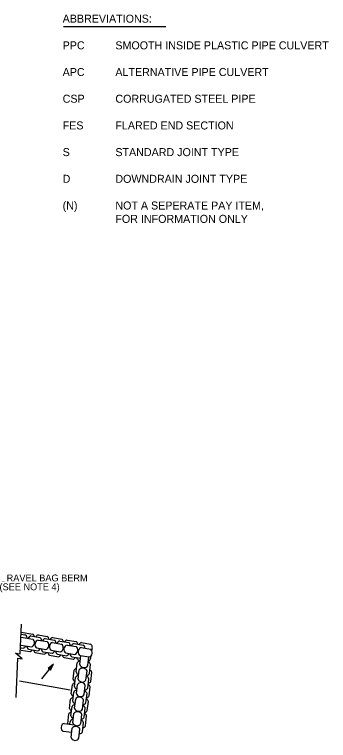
# Model space of a CAD drawing. Extents: x 6707406 to 6714471, y 1868570 to 1872341.
# Drawn here: x 6712803 to 6713078, y 1870297 to 1870932 of the extents above; entities that cross this region are included whole.
import ezdxf

# ---------------------------------------------------------------- set-up
doc = ezdxf.new("R2010")
doc.units = 0
for name, color, linetype in [('56 Stg 3 Anno', 7, 'Continuous'), ('C - SANDBAG', 7, 'Continuous'), ('G-SYMB', 7, 'Continuous'), ('G-TEXT', 7, 'Continuous'), ('Nongeo Data(60)', 7, 'Continuous')]:
    doc.layers.add(name, color=color, linetype=linetype)

msp = doc.modelspace()

# ---------------------------------------------------------------- linework, layer by layer
at = {"layer": '56 Stg 3 Anno'}
for p, q in [((6712837.22, 1870363.81), (6712832.51, 1870360.26)), ((6712832.51, 1870360.26), (6712832.51, 1870360.26)), ((6712832.51, 1870360.26), (6712833.98, 1870360.01)), ((6712836.35, 1870362.8), (6712832.92, 1870360.2)), ((6712835.5, 1870361.79), (6712833.28, 1870360.12)), ((6712834.64, 1870360.78), (6712833.69, 1870360.07)), ((6712834.08, 1870359.71), (6712834.64, 1870360.78)), ((6712834.22, 1870359.37), (6712835.5, 1870361.79)), ((6712834.34, 1870358.97), (6712836.36, 1870362.8)), ((6712834.46, 1870358.59), (6712837.22, 1870363.81)), ((6712837.22, 1870363.81), (6712837.22, 1870363.81)), ((6712833.98, 1870360.01), (6712834.46, 1870358.59)), ((6712834.46, 1870358.59), (6712834.46, 1870358.59))]:
    msp.add_line(p, q, dxfattribs=at)
at = {"layer": 'C - SANDBAG'}
for p, q in [((6712808.83, 1870392.02), (6712819.06, 1870390.25)), ((6712808.83, 1870390.13), (6712811.94, 1870389.59)), ((6712808.83, 1870387.64), (6712818.98, 1870385.84)), ((6712817.36, 1870388.57), (6712825.25, 1870387.19)), ((6712817.36, 1870388.57), (6712825.25, 1870387.19)), ((6712823.8, 1870389.42), (6712831.69, 1870388.04)), ((6712823.8, 1870389.42), (6712831.69, 1870388.04)), ((6712829.99, 1870386.36), (6712837.88, 1870384.98)), ((6712836.43, 1870387.21), (6712844.32, 1870385.83)), ((6712808.83, 1870380.62), (6712817.8, 1870379.05)), ((6712823.73, 1870385.01), (6712831.61, 1870383.63)), ((6712823.73, 1870385.01), (6712831.61, 1870383.63)), ((6712836.36, 1870382.8), (6712844.24, 1870381.42)), ((6712842.62, 1870384.15), (6712850.51, 1870382.77)), ((6712848.98, 1870380.59), (6712856.87, 1870379.21)), ((6712849.06, 1870385), (6712856.94, 1870383.62)), ((6712855.25, 1870381.94), (6712863.14, 1870380.56)), ((6712861.69, 1870382.79), (6712869.57, 1870381.41)), ((6712808.83, 1870378.18), (6712810.6, 1870377.87)), ((6712808.83, 1870376.2), (6712816.37, 1870374.88)), ((6712815.34, 1870377.04), (6712823.23, 1870375.66)), ((6712815.34, 1870377.04), (6712823.23, 1870375.66)), ((6712821.11, 1870374.05), (6712829, 1870372.67)), ((6712821.11, 1870374.05), (6712829, 1870372.67)), ((6712822.54, 1870378.22), (6712830.43, 1870376.84)), ((6712822.54, 1870378.22), (6712830.43, 1870376.84)), ((6712827.97, 1870374.83), (6712835.86, 1870373.45)), ((6712835.17, 1870376.01), (6712843.06, 1870374.63)), ((6712847.8, 1870373.8), (6712855.68, 1870372.42)), ((6712861.61, 1870378.38), (6712869.5, 1870377)), ((6712833.74, 1870371.84), (6712841.63, 1870370.46)), ((6712840.6, 1870372.62), (6712848.49, 1870371.24)), ((6712846.37, 1870369.63), (6712854.25, 1870368.25)), ((6712853.23, 1870370.41), (6712860.88, 1870369.07)), ((6712859, 1870367.42), (6712860.64, 1870367.13)), ((6712860.22, 1870363.62), (6712861.18, 1870371.57)), ((6712860.43, 1870371.59), (6712868.31, 1870370.21)), ((6712867.06, 1870362.79), (6712867.96, 1870370.28)), ((6712857.01, 1870357.07), (6712857.97, 1870365.02)), ((6712868.63, 1870355.67), (6712869.59, 1870363.62)), ((6712854.28, 1870350.73), (6712855.23, 1870358.68)), ((6712858.69, 1870350.89), (6712859.64, 1870358.84)), ((6712865.53, 1870350.06), (6712866.49, 1870358.01)), ((6712869.77, 1870348.86), (6712870.73, 1870356.81)), ((6712855.47, 1870344.34), (6712856.43, 1870352.29)), ((6712867.09, 1870342.94), (6712868.05, 1870350.89)), ((6712852.74, 1870338), (6712853.7, 1870345.95)), ((6712857.15, 1870338.16), (6712858.11, 1870346.11)), ((6712863.99, 1870337.34), (6712864.95, 1870345.29)), ((6712868.24, 1870336.13), (6712869.2, 1870344.08)), ((6712853.94, 1870331.62), (6712854.9, 1870339.56)), ((6712865.56, 1870330.22), (6712866.52, 1870338.16)), ((6712851.21, 1870325.27), (6712852.17, 1870333.22)), ((6712851.21, 1870325.27), (6712852.17, 1870333.22)), ((6712855.62, 1870325.43), (6712856.58, 1870333.38)), ((6712855.62, 1870325.43), (6712856.58, 1870333.38)), ((6712862.46, 1870324.61), (6712863.42, 1870332.56)), ((6712862.46, 1870324.61), (6712863.42, 1870332.56)), ((6712866.7, 1870323.4), (6712867.66, 1870331.35)), ((6712866.7, 1870323.4), (6712867.66, 1870331.35)), ((6712852.41, 1870318.89), (6712853.36, 1870326.84)), ((6712852.41, 1870318.89), (6712853.36, 1870326.84)), ((6712864.03, 1870317.49), (6712864.98, 1870325.44)), ((6712864.03, 1870317.49), (6712864.98, 1870325.44)), ((6712849.6, 1870311.74), (6712850.63, 1870320.49)), ((6712854.08, 1870312.7), (6712855.04, 1870320.65)), ((6712860.93, 1870311.88), (6712861.88, 1870319.83)), ((6712860.93, 1870311.88), (6712861.88, 1870319.83)), ((6712865.1, 1870309.87), (6712866.13, 1870318.62)), ((6712846.37, 1870312.08), (6712855.12, 1870311.02)), ((6712851.44, 1870311.47), (6712851.67, 1870313.42)), ((6712862.49, 1870304.76), (6712863.45, 1870312.71)), ((6712845.55, 1870305.23), (6712853.06, 1870304.33)), ((6712852.53, 1870299.92), (6712853.49, 1870307.87)), ((6712859.38, 1870299.1), (6712860.33, 1870307.05))]:
    msp.add_line(p, q, dxfattribs=at)
for centre, major_axis, ratio, start_param, end_param in [((6712811.45, 1870385.87), (-0.65, -3.7), 0.71077, 1.915159, 3.202147), ((6712817.25, 1870384.85), (-0.59, -3.7), 0.711359, 3.317588, 4.350526), ((6712817.25, 1870384.85), (-0.59, -3.7), 0.711359, 3.317588, 4.29466), ((6712817.82, 1870382.32), (-0.65, -3.7), 0.71077, 1.662213, 2.935943), ((6712817.94, 1870386.71), (-0.59, -3.71), 0.71077, 2.038051, 2.935943), ((6712823.68, 1870385.71), (-0.59, -3.7), 0.711359, 3.317588, 4.221159), ((6712823.68, 1870385.71), (-0.59, -3.7), 0.711359, 3.317588, 4.221159), ((6712824.08, 1870383.66), (-0.65, -3.7), 0.71077, 1.915159, 2.935943), ((6712824.08, 1870383.66), (-0.65, -3.7), 0.71077, 1.915159, 2.935943), ((6712829.87, 1870382.64), (-0.59, -3.7), 0.711359, 3.317588, 4.353284), ((6712830.57, 1870384.5), (-0.59, -3.71), 0.71077, 2.038051, 2.935943), ((6712830.57, 1870384.5), (-0.59, -3.71), 0.71077, 2.038051, 2.935943), ((6712836.31, 1870383.5), (-0.59, -3.7), 0.711359, 3.317588, 4.221159), ((6712843.2, 1870382.29), (-0.59, -3.71), 0.71077, 2.038051, 2.935943), ((6712810.7, 1870381.58), (0.65, 3.7), 0.71077, 3.347242, 4.368026), ((6712816.5, 1870380.58), (0.71, 3.68), 0.711359, 1.929645, 2.965597), ((6712816.5, 1870380.58), (0.71, 3.68), 0.711359, 1.988526, 2.965597), ((6712817.89, 1870382.77), (0.65, 3.7), 0.71077, 3.347242, 4.682592), ((6712823.63, 1870381.78), (0.65, 3.69), 0.711359, 1.636191, 2.965597), ((6712823.63, 1870381.78), (0.65, 3.69), 0.711359, 1.636191, 2.965597), ((6712823.55, 1870381.3), (-0.65, -3.69), 0.711359, 3.317588, 4.646994), ((6712823.55, 1870381.3), (-0.65, -3.69), 0.711359, 3.317588, 4.646994), ((6712830.52, 1870380.56), (0.65, 3.7), 0.71077, 3.347242, 4.682592), ((6712830.52, 1870380.56), (0.65, 3.7), 0.71077, 3.347242, 4.682592), ((6712830.44, 1870380.11), (-0.65, -3.7), 0.71077, 1.662213, 2.935943), ((6712830.44, 1870380.11), (-0.65, -3.7), 0.71077, 1.662213, 2.935943), ((6712836.26, 1870379.57), (0.65, 3.69), 0.711359, 1.636191, 2.965597), ((6712836.18, 1870379.09), (-0.65, -3.69), 0.711359, 3.317588, 4.646994), ((6712836.71, 1870381.45), (-0.65, -3.7), 0.71077, 1.915159, 2.935943), ((6712842.5, 1870380.43), (-0.59, -3.7), 0.711359, 3.317588, 4.353284), ((6712843.07, 1870377.9), (-0.65, -3.7), 0.71077, 1.662213, 2.935943), ((6712848.81, 1870376.88), (-0.65, -3.69), 0.711359, 3.317588, 4.646994), ((6712848.94, 1870381.29), (-0.59, -3.7), 0.711359, 3.317588, 4.221159), ((6712849.34, 1870379.24), (-0.65, -3.7), 0.71077, 1.915159, 2.935943), ((6712855.13, 1870378.22), (-0.59, -3.7), 0.711359, 3.317588, 4.353284), ((6712855.7, 1870375.69), (-0.65, -3.7), 0.71077, 1.662213, 2.935943), ((6712855.83, 1870380.08), (-0.59, -3.71), 0.71077, 2.038051, 2.935943), ((6712861.57, 1870379.08), (-0.59, -3.7), 0.711359, 3.317588, 4.221159), ((6712861.97, 1870377.03), (-0.65, -3.7), 0.71077, 1.915159, 2.935943), ((6712868.46, 1870377.87), (-0.59, -3.71), 0.71077, 1.123773, 2.935943), ((6712816.52, 1870378.59), (0.71, 3.68), 0.71077, 3.347242, 4.244863), ((6712822.26, 1870377.59), (0.71, 3.68), 0.711359, 2.062027, 2.965597), ((6712822.26, 1870377.59), (0.71, 3.68), 0.711359, 2.062027, 2.965597), ((6712823.33, 1870379.37), (0.65, 3.7), 0.71077, 3.347242, 4.368026), ((6712823.33, 1870379.37), (0.65, 3.7), 0.71077, 3.347242, 4.368026), ((6712829.13, 1870378.37), (0.71, 3.68), 0.711359, 1.929645, 2.965597), ((6712829.15, 1870376.38), (0.71, 3.68), 0.71077, 3.347242, 4.244863), ((6712829.15, 1870376.38), (0.71, 3.68), 0.71077, 3.347242, 4.244863), ((6712834.89, 1870375.38), (0.71, 3.68), 0.711359, 2.062027, 2.965597), ((6712835.96, 1870377.16), (0.65, 3.7), 0.71077, 3.347242, 4.368026), ((6712841.76, 1870376.16), (0.71, 3.68), 0.711359, 1.929645, 2.965597), ((6712843.15, 1870378.35), (0.65, 3.7), 0.71077, 3.347242, 4.682592), ((6712848.89, 1870377.36), (0.65, 3.69), 0.711359, 1.636191, 2.965597), ((6712848.59, 1870374.95), (0.65, 3.7), 0.71077, 3.347242, 4.368026), ((6712854.38, 1870373.95), (0.71, 3.68), 0.711359, 1.929645, 2.965597), ((6712855.78, 1870376.14), (0.65, 3.7), 0.71077, 3.347242, 4.682592), ((6712861.52, 1870375.15), (0.65, 3.69), 0.711359, 1.636191, 2.965597), ((6712861.44, 1870374.67), (-0.65, -3.69), 0.711359, 3.317588, 4.646994), ((6712868.41, 1870373.93), (0.65, 3.7), 0.71077, 3.347242, 4.682592), ((6712868.33, 1870373.48), (-0.65, -3.7), 0.71077, 1.662213, 2.935943), ((6712841.78, 1870374.17), (0.71, 3.68), 0.71077, 3.347242, 4.244863), ((6712847.52, 1870373.17), (0.71, 3.68), 0.711359, 2.062027, 2.965597), ((6712854.41, 1870371.96), (0.71, 3.68), 0.71077, 3.347242, 4.244863), ((6712860.15, 1870370.96), (0.71, 3.68), 0.711359, 2.062027, 2.965597), ((6712861.55, 1870364.04), (3.72, -0.45), 0.71077, 1.915159, 2.935943), ((6712867.04, 1870369.75), (0.71, 3.68), 0.71077, 3.564653, 5.159412), ((6712858.83, 1870357.75), (3.73, -0.39), 0.71077, 2.038051, 2.935943), ((6712863.23, 1870357.86), (3.72, -0.45), 0.71077, 1.662213, 2.935943), ((6712863.94, 1870363.64), (3.72, -0.45), 0.711359, 3.317588, 4.646994), ((6712862.77, 1870357.91), (-3.72, 0.45), 0.71077, 3.347242, 4.682592), ((6712863.45, 1870363.7), (-3.72, 0.45), 0.711359, 1.636191, 2.965597), ((6712865.87, 1870363.52), (-3.72, 0.45), 0.71077, 3.347242, 4.368026), ((6712860.01, 1870351.31), (3.72, -0.45), 0.71077, 1.915159, 2.935943), ((6712860.73, 1870357.15), (3.73, -0.39), 0.711359, 3.317588, 4.353284), ((6712865.03, 1870356.64), (-3.71, 0.51), 0.711359, 1.929645, 2.965597), ((6712867.02, 1870356.77), (-3.72, 0.51), 0.71077, 3.347242, 4.244863), ((6712857.3, 1870345.03), (3.73, -0.39), 0.71077, 2.038051, 2.935943), ((6712858, 1870350.81), (3.73, -0.39), 0.711359, 3.317588, 4.221159), ((6712861.69, 1870345.13), (3.72, -0.45), 0.71077, 1.662213, 2.935943), ((6712862.41, 1870350.91), (3.72, -0.45), 0.711359, 3.317588, 4.646994), ((6712861.24, 1870345.18), (-3.72, 0.45), 0.71077, 3.347242, 4.682592), ((6712861.92, 1870350.97), (-3.72, 0.45), 0.711359, 1.636191, 2.965597), ((6712864.34, 1870350.79), (-3.72, 0.45), 0.71077, 3.347242, 4.368026), ((6712866.18, 1870349.82), (-3.71, 0.51), 0.711359, 2.062027, 2.965597), ((6712858.48, 1870338.59), (3.72, -0.45), 0.71077, 1.915159, 2.935943), ((6712859.19, 1870344.43), (3.73, -0.39), 0.711359, 3.317588, 4.353284), ((6712863.5, 1870343.91), (-3.71, 0.51), 0.711359, 1.929645, 2.965597), ((6712865.48, 1870344.04), (-3.72, 0.51), 0.71077, 3.347242, 4.244863), ((6712855.76, 1870332.3), (3.73, -0.39), 0.71077, 2.038051, 2.935943), ((6712855.76, 1870332.3), (3.73, -0.39), 0.71077, 2.038051, 2.935943), ((6712856.46, 1870338.08), (3.73, -0.39), 0.711359, 3.317588, 4.221159), ((6712860.16, 1870332.4), (3.72, -0.45), 0.71077, 1.662213, 2.935943), ((6712860.16, 1870332.4), (3.72, -0.45), 0.71077, 1.662213, 2.935943), ((6712860.87, 1870338.18), (3.72, -0.45), 0.711359, 3.317588, 4.646994), ((6712859.71, 1870332.46), (-3.72, 0.45), 0.71077, 3.347242, 4.682592), ((6712859.71, 1870332.46), (-3.72, 0.45), 0.71077, 3.347242, 4.682592), ((6712860.39, 1870338.24), (-3.72, 0.45), 0.711359, 1.636191, 2.965597), ((6712862.81, 1870338.06), (-3.72, 0.45), 0.71077, 3.347242, 4.368026), ((6712864.65, 1870337.09), (-3.71, 0.51), 0.711359, 2.062027, 2.965597), ((6712856.95, 1870325.86), (3.72, -0.45), 0.71077, 1.915159, 2.935943), ((6712856.95, 1870325.86), (3.72, -0.45), 0.71077, 1.915159, 2.935943), ((6712857.66, 1870331.7), (3.73, -0.39), 0.711359, 3.317588, 4.353284), ((6712861.97, 1870331.18), (-3.71, 0.51), 0.711359, 1.929645, 2.965597), ((6712863.95, 1870331.31), (-3.72, 0.51), 0.71077, 3.347242, 4.244863), ((6712863.95, 1870331.31), (-3.72, 0.51), 0.71077, 3.347242, 4.244863), ((6712854.23, 1870319.57), (3.73, -0.39), 0.71077, 2.038051, 2.935943), ((6712854.93, 1870325.35), (3.73, -0.39), 0.711359, 3.317588, 4.221159), ((6712854.93, 1870325.35), (3.73, -0.39), 0.711359, 3.317588, 4.221159), ((6712858.62, 1870319.67), (3.72, -0.45), 0.71077, 1.662213, 2.935943), ((6712859.34, 1870325.45), (3.72, -0.45), 0.711359, 3.317588, 4.646994), ((6712859.34, 1870325.45), (3.72, -0.45), 0.711359, 3.317588, 4.646994), ((6712858.17, 1870319.73), (-3.72, 0.45), 0.71077, 3.347242, 4.682592), ((6712858.85, 1870325.51), (-3.72, 0.45), 0.711359, 1.636191, 2.965597), ((6712858.85, 1870325.51), (-3.72, 0.45), 0.711359, 1.636191, 2.965597), ((6712861.27, 1870325.34), (-3.72, 0.45), 0.71077, 3.347242, 4.368026), ((6712861.27, 1870325.34), (-3.72, 0.45), 0.71077, 3.347242, 4.368026), ((6712863.11, 1870324.36), (-3.71, 0.51), 0.711359, 2.062027, 2.965597), ((6712863.11, 1870324.36), (-3.71, 0.51), 0.711359, 2.062027, 2.965597), ((6712855.41, 1870313.13), (3.72, -0.45), 0.71077, 1.915159, 3.202147), ((6712856.13, 1870318.97), (3.73, -0.39), 0.711359, 3.317588, 4.350526), ((6712856.13, 1870318.97), (3.73, -0.39), 0.711359, 3.317588, 4.29466), ((6712860.43, 1870318.45), (-3.71, 0.51), 0.711359, 1.929645, 2.965597), ((6712860.43, 1870318.45), (-3.71, 0.51), 0.711359, 1.988526, 2.965597), ((6712862.42, 1870318.58), (-3.72, 0.51), 0.71077, 3.347242, 4.244863), ((6712846.39, 1870308.36), (-0.45, -3.72), 0.711359, 3.317588, 4.646994), ((6712857.07, 1870306.89), (3.72, -0.45), 0.71077, 1.662213, 2.935943), ((6712857.8, 1870312.72), (3.72, -0.45), 0.711359, 3.317588, 4.646994), ((6712856.62, 1870306.95), (-3.72, 0.45), 0.71077, 3.347242, 4.682592), ((6712857.32, 1870312.78), (-3.72, 0.45), 0.711359, 1.636191, 2.965597), ((6712859.74, 1870312.61), (-3.72, 0.45), 0.71077, 3.347242, 4.368026), ((6712861.5, 1870310.84), (-3.71, 0.51), 0.711359, 2.062027, 2.965597), ((6712846.45, 1870308.84), (0.45, 3.72), 0.711359, 1.636191, 2.965597), ((6712858.9, 1870305.72), (-3.71, 0.51), 0.711359, 1.929645, 2.965597), ((6712856.25, 1870299.94), (3.72, -0.45), 0.711359, 3.317588, 4.646994), ((6712855.77, 1870300), (-3.72, 0.45), 0.711359, 1.636191, 2.965597)]:
    msp.add_ellipse(centre, major_axis=major_axis, ratio=ratio, start_param=start_param, end_param=end_param, dxfattribs=at)
at = {"layer": 'G-SYMB'}
for p, q in [((6712808.08, 1870373.09), (6712809.13, 1870398.87)), ((6712808.08, 1870373.09), (6712808.08, 1870373.09)), ((6712805.6, 1870369.25), (6712804.19, 1870334.79)), ((6712805.6, 1870369.25), (6712805.6, 1870369.25)), ((6712834, 1870360.01), (6712826.65, 1870351.04)), ((6712807.54, 1870349.27), (6712851.74, 1870341.53))]:
    msp.add_line(p, q, dxfattribs=at)
msp.add_lwpolyline([(6712805.6, 1870369.25), (6712809.8, 1870368.72), (6712803.88, 1870373.62), (6712808.08, 1870373.09)], dxfattribs=at)
msp.add_lwpolyline([(6712806.84, 1870371.17), (6712806.84, 1870371.17)], close=True, dxfattribs=at)
at = {"layer": 'Nongeo Data(60)'}
msp.add_line((6712845.89, 1870921.24), (6712935.52, 1870921.24), dxfattribs=at)

# ---------------------------------------------------------------- texts
at = {"layer": 'G-TEXT'}
for s, p in [('GRAVEL BAG BERM', (6712789.91, 1870436.27)), ('(SEE NOTE 4)', (6712789.91, 1870428.51))]:
    msp.add_text(s, height=6, rotation=360, dxfattribs=at).set_placement(p)
at = {"layer": 'Nongeo Data(60)'}
for s, height, p in [('ABBREVIATIONS:', 7.0002, (6712845.17, 1870924.68)), ('PPC', 7, (6712845.17, 1870901.34)), ('SMOOTH INSIDE PLASTIC PIPE CULVERT', 7.0002, (6712891.3, 1870901.33)), ('APC', 7, (6712845.17, 1870878.01)), ('ALTERNATIVE PIPE CULVERT', 7.0002, (6712891.3, 1870878)), ('CSP', 7, (6712845.17, 1870854.67)), ('CORRUGATED STEEL PIPE', 7.0002, (6712891.3, 1870854.66)), ('FES', 7, (6712845.17, 1870831.34)), ('FLARED END SECTION', 7.0002, (6712891.3, 1870831.33)), ('S', 7, (6712845.17, 1870808.01)), ('STANDARD JOINT TYPE', 7.0002, (6712891.3, 1870807.99)), ('D', 7, (6712845.17, 1870784.67)), ('DOWNDRAIN JOINT TYPE', 7.0002, (6712891.3, 1870784.66)), ('(N)', 7, (6712845.17, 1870761.34)), ('NOT A SEPERATE PAY ITEM, ', 7.0002, (6712891.3, 1870761.33)), ('FOR INFORMATION ONLY', 7.0002, (6712891.3, 1870749.66))]:
    msp.add_text(s, height=height, rotation=0.00001, dxfattribs=at).set_placement(p)

doc.saveas('drawing.dxf')
